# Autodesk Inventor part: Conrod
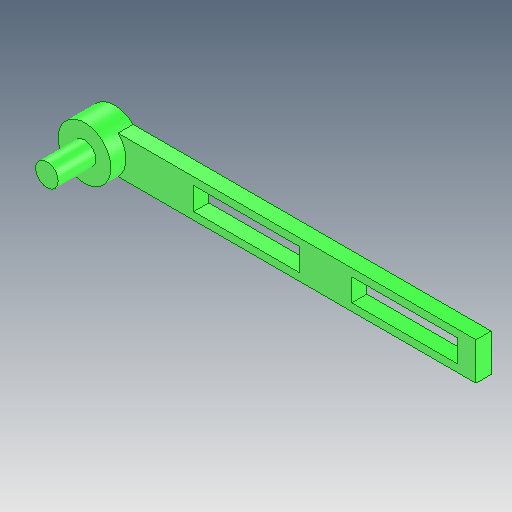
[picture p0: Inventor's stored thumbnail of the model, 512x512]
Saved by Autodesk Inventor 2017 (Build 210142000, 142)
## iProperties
Created: 2018-04
Part Number: Conrod
Document SubType Name: Modeling
Designer: Administrator
Density: 1 g/cm^3
Mass: 3.91916 g
Surface Area: 33.5141 cm^2
Volume: 3.91916 cm^3
Material: Generic
Appearance: LED - Green On
Author: Administrator
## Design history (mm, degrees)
sketch "Sketch1"
  geometry: L1 (0, 0)-(100, 0); L2 (4.899, 5)-(100, 5); L3 (4.899, -5)-(100, -5); L4 (100, 0)-(100, -6.107); L5 (100, 0)-(100, 6.038); L6 (100, 3)-(25, 3); L7 (25, 3)-(25, -3); L8 (25, -3)-(100, -3); L9 (100, -3)-(100, 3); L10 (62.5, 3)-(62.5, 0); L11 (62.5, 0)-(62.5, -3); L12 (25, -3)-(53, -3); L13 (53, -3)-(53, 3); L14 (53, 3)-(25, 3); L15 (25, 3)-(25, -3); L16 (95, -3)-(67, -3); L17 (67, -3)-(67, 3); L18 (67, 3)-(95, 3); L19 (95, 3)-(95, -3); C1 r 3 at (0, 0); A1 r 7 centre (0, 0) between (4.899, 5) and (4.899, -5)
  constraints: 38 end point, 8 parallel, 8 point on line, 4 horizontal, 4 perpendicular, 2 centre point, 2 coincident, 2 midpoint, 2 point on circle, 1 collinear, 1 vertical, 1 other
  dimensions: "d0" = 100 distance of L1.start L1.end; "d1" = 6 diameter of C1; "d2" = 14 diameter of A1; "d3" = 10 distance between parallel lines of L2 L3; "d8" = 6 distance between parallel lines of L6 L8; "d9" = 5 distance between parallel lines of L19 L5; "d10" = 28 distance between parallel lines of L17 L19; "d11" = 25 distance from line of L7 L1.start; "d12" = 28 distance between parallel lines of L13 L7
extrude "Extrusion3" new body sketch "Sketch1" distance "d13" = 4; taper "d14" = 0 deg
sketch "Sketch3"
  geometry: C1 r 3 at (0, 0); 1 further point
  constraints: 1 centre point, 1 coincident
  dimensions: "d15" = 6 diameter of C1
extrude "Extrusion4" join sketch "Sketch3" distance "d16" = 14; taper "d17" = 0 deg
sketch "Sketch4"
  geometry: L1 (67, -3)-(67, 3) reference; L2 (67, 3)-(95, 3) reference; L3 (95, 3)-(95, -3) reference; L4 (95, -3)-(67, -3) reference; L5 (25, -3)-(25, 3) reference; L6 (25, 3)-(53, 3) reference; L7 (53, 3)-(53, -3) reference; L8 (53, -3)-(25, -3) reference; L9 (100, -5)-(100, 5) reference; L10 (100, 5)-(4.899, 5) reference; L11 (4.899, -5)-(100, -5) reference; C1 r 3 at (0, 0) reference; C2 r 7 at (0, 0); A1 r 7 centre (0, 0) between (4.899, 5) and (4.899, -5) reference; 1 further point
  constraints: 1 centre point, 1 coincident
  dimensions: "d18" = 14 diameter of C2
extrude "Extrusion5" join sketch "Sketch4" distance "d19" = 4; taper "d20" = 0 deg
sketch "Sketch5"
  geometry: L1 (-67, 3)-(-67, -3) reference; L2 (-67, -3)-(-95, -3) reference; L3 (-95, -3)-(-95, 3) reference; L4 (-95, 3)-(-67, 3) reference; L5 (-25, 3)-(-25, -3) reference; L6 (-25, -3)-(-53, -3) reference; L7 (-53, -3)-(-53, 3) reference; L8 (-53, 3)-(-25, 3) reference; L9 (-100, 5)-(-100, -5) reference; L10 (-100, -5)-(-4.899, -5) reference; L11 (-4.899, 5)-(-100, 5) reference; C1 r 3 at (0, 0) reference; A1 r 7 centre (0, 0) between (-4.899, -5) and (-4.899, 5) reference; 1 further point
extrude "Extrusion6" join sketch "Sketch5" distance "d21" = 4.1; taper "d22" = 0 deg
body "Solid2"
node "Projected Loop1"
node "Projected Loop2"
